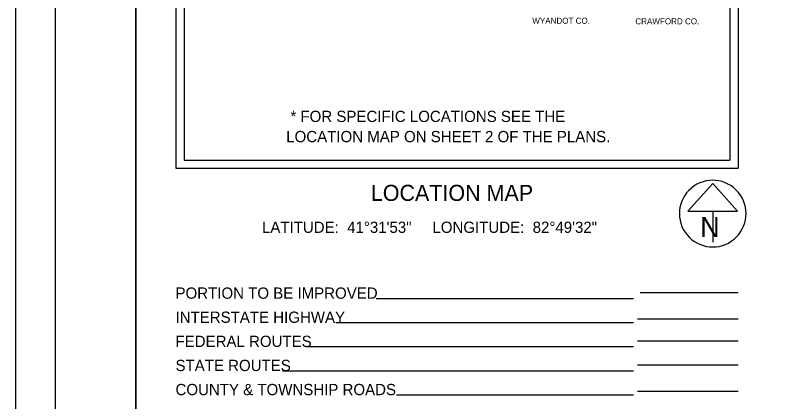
# Model space of a CAD drawing. Extents: x 0 to 34, y 0 to 22.
# Drawn here: x 0 to 9.58, y 11.1 to 15.9 of the extents above; entities that cross this region are included whole.
import ezdxf

# ---------------------------------------------------------------- set-up
doc = ezdxf.new("R2010")
doc.units = 0
for name, color, linetype in [('SH_Border', 7, 'Continuous'), ('SH_Cut_Line', 7, 'Continuous'), ('SH_Data', 7, 'Continuous'), ('SH_Text', 7, 'Continuous')]:
    doc.layers.add(name, color=color, linetype=linetype)

msp = doc.modelspace()

# ---------------------------------------------------------------- linework, layer by layer
at = {"layer": 'SH_Border'}
for points in [[(0.5, 21.5), (1.5, 21.5), (1.5, 0.5), (0.5, 0.5)], [(1.5, 21.5), (33.5, 21.5), (33.5, 0.5), (1.5, 0.5)]]:
    msp.add_lwpolyline(points, close=True, dxfattribs=at)
at = {"layer": 'SH_Cut_Line'}
msp.add_lwpolyline([(0, 0), (34, 0), (34, 22), (0, 22)], close=True, dxfattribs=at)
at = {"layer": 'SH_Data'}
for p, q in [((2, 21), (2, 14)), ((9, 21), (9, 14)), ((2.1, 20.9), (2.1, 14.1)), ((8.9, 20.9), (8.9, 14.1)), ((2.1, 14.1), (8.9, 14.1)), ((2.1, 14.1), (2.1, 14.1)), ((2, 14), (9, 14)), ((8.6845, 13.8091), (8.3769, 13.4678)), ((8.9921, 13.4678), (8.6845, 13.8091)), ((8.3769, 13.4678), (8.9921, 13.4678)), ((8.6845, 13.4678), (8.6845, 13.0811)), ((8.6845, 13.4353), (8.6845, 13.4353)), ((8.6845, 13.4353), (8.6845, 13.4353)), ((7.7827, 12.4553), (9, 12.4553)), ((7.7, 12.3767), (4.4937, 12.3767)), ((7.7, 12.0767), (3.9895, 12.0767)), ((9, 12.1207), (7.75, 12.1207)), ((9, 11.8491), (7.75, 11.8491)), ((7.7, 11.7767), (3.6192, 11.7767)), ((9, 11.5491), (7.75, 11.5491)), ((7.7, 11.4767), (3.3288, 11.4767)), ((9, 11.2223), (7.75, 11.2223)), ((7.7, 11.1767), (4.7452, 11.1767))]:
    msp.add_line(p, q, dxfattribs=at)
msp.add_arc((8.6845, 13.4353), 0.4148, 129.77984, 129.76332, dxfattribs=at)

# ---------------------------------------------------------------- texts
for s, height, p in [('WYANDOT CO.', 0.075, (6.4374, 15.7978)), ('CRAWFORD CO.', 0.075, (7.721, 15.791)), (' * FOR SPECIFIC LOCATIONS SEE THE ', 0.14, (3.3734, 14.5754)), ('LOCATION MAP ON SHEET 2 OF THE PLANS.', 0.14, (3.3734, 14.3244)), ('N', 0.25, (8.5292, 13.144))]:
    msp.add_text(s, height=height, dxfattribs=at).set_placement(p)
at = {"layer": 'SH_Text'}
for s, height, p in [('LOCATION MAP', 0.2, (4.4269, 13.5938)), ('LATITUDE:  41°31\'53"     LONGITUDE:  82°49\'32"', 0.14, (3.071, 13.1959)), ('PORTION TO BE IMPROVED', 0.14, (1.9944, 12.3767)), ('INTERSTATE HIGHWAY', 0.14, (1.9944, 12.0767)), ('FEDERAL ROUTES', 0.14, (1.9944, 11.7767)), ('STATE ROUTES', 0.14, (1.9944, 11.4767)), ('COUNTY & TOWNSHIP ROADS', 0.14, (1.9944, 11.1767))]:
    msp.add_text(s, height=height, dxfattribs=at).set_placement(p)

doc.saveas('drawing.dxf')
